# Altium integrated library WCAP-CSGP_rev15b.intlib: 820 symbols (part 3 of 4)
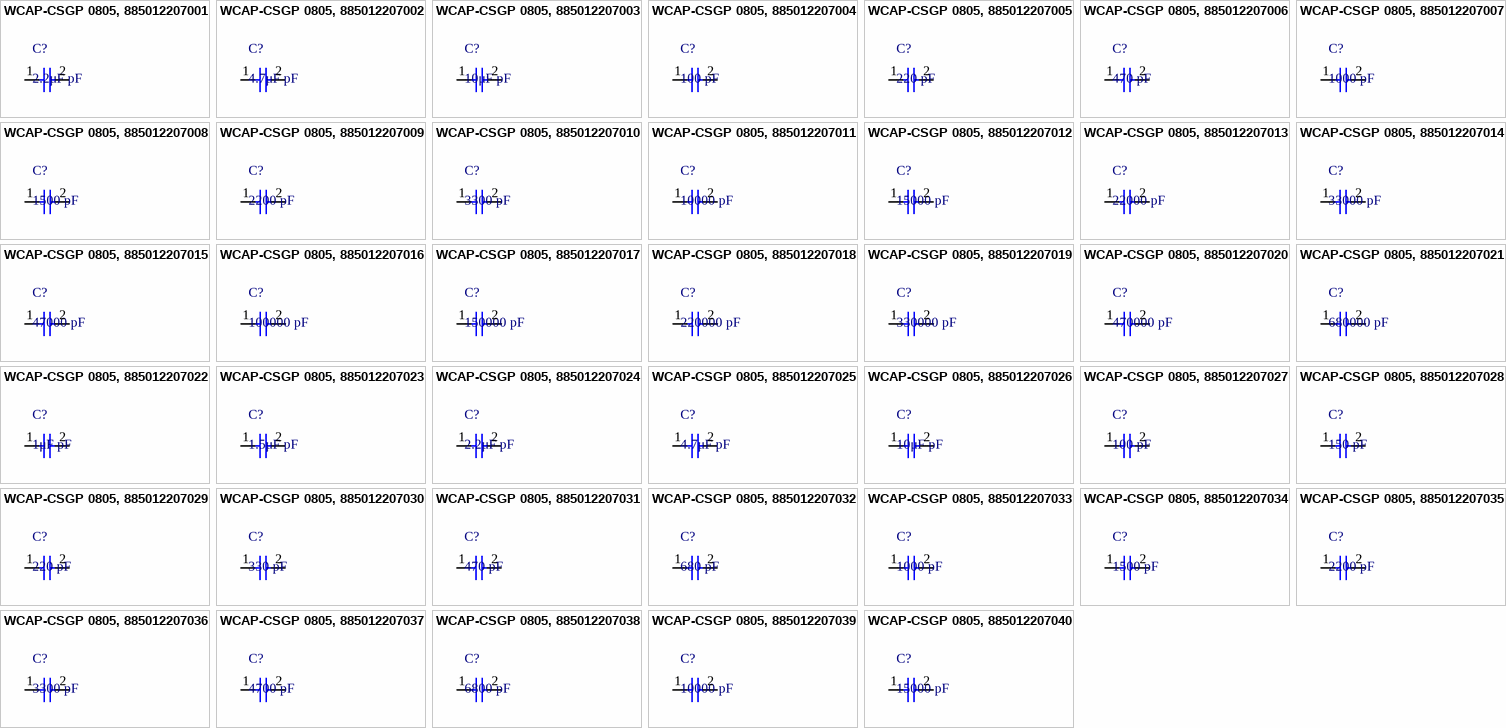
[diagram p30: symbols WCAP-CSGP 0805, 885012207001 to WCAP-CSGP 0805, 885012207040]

## WCAP-CSGP 0805, 885012207004
designator C?, comment 100 pF
WCAP-CSGP MLCC, X7R, 0805, 100 pF,10Vdc; Manufacturer: Wurth Elektronik; partNo: 885012207004; E-mail: libraries@we-online.com
footprint WCAP-CSGP 0805, H=0.8mm
pins: 1, 2

## WCAP-CSGP 0805, 885012207005
designator C?, comment 220 pF
WCAP-CSGP MLCC, X7R, 0805, 220 pF,10Vdc; Manufacturer: Wurth Elektronik; partNo: 885012207005; E-mail: libraries@we-online.com
footprint WCAP-CSGP 0805, H=0.8mm
pins: 1, 2

## WCAP-CSGP 0805, 885012207006
designator C?, comment 470 pF
WCAP-CSGP MLCC, X7R, 0805, 470 pF,10Vdc; Manufacturer: Wurth Elektronik; partNo: 885012207006; E-mail: libraries@we-online.com
footprint WCAP-CSGP 0805, H=0.8mm
pins: 1, 2

## WCAP-CSGP 0805, 885012207007
designator C?, comment 1000 pF
WCAP-CSGP MLCC, X7R, 0805, 1000 pF,10Vdc; Manufacturer: Wurth Elektronik; partNo: 885012207007; E-mail: libraries@we-online.com
footprint WCAP-CSGP 0805, H=0.8mm
pins: 1, 2

## WCAP-CSGP 0805, 885012207008
designator C?, comment 1500 pF
WCAP-CSGP MLCC, X7R, 0805, 1500 pF,10Vdc; Manufacturer: Wurth Elektronik; partNo: 885012207008; E-mail: libraries@we-online.com
footprint WCAP-CSGP 0805, H=0.8mm
pins: 1, 2

## WCAP-CSGP 0805, 885012207009
designator C?, comment 2200 pF
WCAP-CSGP MLCC, X7R, 0805, 2200 pF,10Vdc; Manufacturer: Wurth Elektronik; partNo: 885012207009; E-mail: libraries@we-online.com
footprint WCAP-CSGP 0805, H=0.8mm
pins: 1, 2

## WCAP-CSGP 0805, 885012207010
designator C?, comment 3300 pF
WCAP-CSGP MLCC, X7R, 0805, 3300 pF,10Vdc; Manufacturer: Wurth Elektronik; partNo: 885012207010; E-mail: libraries@we-online.com
footprint WCAP-CSGP 0805, H=0.8mm
pins: 1, 2

## WCAP-CSGP 0805, 885012207011
designator C?, comment 10000 pF
WCAP-CSGP MLCC, X7R, 0805, 10000 pF,10Vdc; Manufacturer: Wurth Elektronik; partNo: 885012207011; E-mail: libraries@we-online.com
footprint WCAP-CSGP 0805, H=0.8mm
pins: 1, 2

## WCAP-CSGP 0805, 885012207012
designator C?, comment 15000 pF
WCAP-CSGP MLCC, X7R, 0805, 15000 pF,10Vdc; Manufacturer: Wurth Elektronik; partNo: 885012207012; E-mail: libraries@we-online.com
footprint WCAP-CSGP 0805, H=0.8mm
pins: 1, 2

## WCAP-CSGP 0805, 885012207013
designator C?, comment 22000 pF
WCAP-CSGP MLCC, X7R, 0805, 22000 pF,10Vdc; Manufacturer: Wurth Elektronik; partNo: 885012207013; E-mail: libraries@we-online.com
footprint WCAP-CSGP 0805, H=0.8mm
pins: 1, 2

## WCAP-CSGP 0805, 885012207014
designator C?, comment 33000 pF
WCAP-CSGP MLCC, X7R, 0805, 33000 pF,10Vdc; Manufacturer: Wurth Elektronik; partNo: 885012207014; E-mail: libraries@we-online.com
footprint WCAP-CSGP 0805, H=0.8mm
pins: 1, 2

## WCAP-CSGP 0805, 885012207015
designator C?, comment 47000 pF
WCAP-CSGP MLCC, X7R, 0805, 47000 pF,10Vdc; Manufacturer: Wurth Elektronik; partNo: 885012207015; E-mail: libraries@we-online.com
footprint WCAP-CSGP 0805, H=0.8mm
pins: 1, 2

## WCAP-CSGP 0805, 885012207016
designator C?, comment 100000 pF
WCAP-CSGP MLCC, X7R, 0805, 100000 pF,10Vdc; Manufacturer: Wurth Elektronik; partNo: 885012207016; E-mail: libraries@we-online.com
footprint WCAP-CSGP 0805, H=0.8mm
pins: 1, 2

## WCAP-CSGP 0805, 885012207017
designator C?, comment 150000 pF
WCAP-CSGP MLCC, X7R, 0805, 150000 pF,10Vdc; Manufacturer: Wurth Elektronik; partNo: 885012207017; E-mail: libraries@we-online.com
footprint WCAP-CSGP 0805, H=1.25mm
pins: 1, 2

## WCAP-CSGP 0805, 885012207018
designator C?, comment 220000 pF
WCAP-CSGP MLCC, X7R, 0805, 220000 pF,10Vdc; Manufacturer: Wurth Elektronik; partNo: 885012207018; E-mail: libraries@we-online.com
footprint WCAP-CSGP 0805, H=1.25mm
pins: 1, 2

## WCAP-CSGP 0805, 885012207019
designator C?, comment 330000 pF
WCAP-CSGP MLCC, X7R, 0805, 330000 pF,10Vdc; Manufacturer: Wurth Elektronik; partNo: 885012207019; E-mail: libraries@we-online.com
footprint WCAP-CSGP 0805, H=1.25mm
pins: 1, 2

## WCAP-CSGP 0805, 885012207020
designator C?, comment 470000 pF
WCAP-CSGP MLCC, X7R, 0805, 470000 pF,10Vdc; Manufacturer: Wurth Elektronik; partNo: 885012207020; E-mail: libraries@we-online.com
footprint WCAP-CSGP 0805, H=1.25mm
pins: 1, 2

## WCAP-CSGP 0805, 885012207021
designator C?, comment 680000 pF
WCAP-CSGP MLCC, X7R, 0805, 680000 pF,10Vdc; Manufacturer: Wurth Elektronik; partNo: 885012207021; E-mail: libraries@we-online.com
footprint WCAP-CSGP 0805, H=1.25mm
pins: 1, 2

## WCAP-CSGP 0805, 885012207022
designator C?, comment 1μF pF
WCAP-CSGP MLCC, X7R, 0805, 1μF pF,10Vdc; Manufacturer: Wurth Elektronik; partNo: 885012207022; E-mail: libraries@we-online.com
footprint WCAP-CSGP 0805, H=1.25mm
pins: 1, 2

## WCAP-CSGP 0805, 885012207023
designator C?, comment 1.5μF pF
WCAP-CSGP MLCC, X7R, 0805, 1.5μF pF,10Vdc; Manufacturer: Wurth Elektronik; partNo: 885012207023; E-mail: libraries@we-online.com
footprint WCAP-CSGP 0805, H=1.25mm
pins: 1, 2

## WCAP-CSGP 0805, 885012207024
designator C?, comment 2.2μF pF
WCAP-CSGP MLCC, X7R, 0805, 2.2μF pF,10Vdc; Manufacturer: Wurth Elektronik; partNo: 885012207024; E-mail: libraries@we-online.com
footprint WCAP-CSGP 0805, H=1.25mm
pins: 1, 2

## WCAP-CSGP 0805, 885012207025
designator C?, comment 4.7μF pF
WCAP-CSGP MLCC, X7R, 0805, 4.7μF pF,10Vdc; Manufacturer: Wurth Elektronik; partNo: 885012207025; E-mail: libraries@we-online.com
footprint WCAP-CSGP 0805, H=1.25mm
pins: 1, 2

## WCAP-CSGP 0805, 885012207026
designator C?, comment 10μF pF
WCAP-CSGP MLCC, X7R, 0805, 10μF pF,10Vdc; Manufacturer: Wurth Elektronik; partNo: 885012207026; E-mail: libraries@we-online.com
footprint WCAP-CSGP 0805, H=1.25mm
pins: 1, 2

## WCAP-CSGP 0805, 885012207027
designator C?, comment 100 pF
WCAP-CSGP MLCC, X7R, 0805, 100 pF,16Vdc; Manufacturer: Wurth Elektronik; partNo: 885012207027; E-mail: libraries@we-online.com
footprint WCAP-CSGP 0805, H=0.8mm
pins: 1, 2

## WCAP-CSGP 0805, 885012207028
designator C?, comment 150 pF
WCAP-CSGP MLCC, X7R, 0805, 150 pF,16Vdc; Manufacturer: Wurth Elektronik; partNo: 885012207028; E-mail: libraries@we-online.com
footprint WCAP-CSGP 0805, H=0.8mm
pins: 1, 2

## WCAP-CSGP 0805, 885012207029
designator C?, comment 220 pF
WCAP-CSGP MLCC, X7R, 0805, 220 pF,16Vdc; Manufacturer: Wurth Elektronik; partNo: 885012207029; E-mail: libraries@we-online.com
footprint WCAP-CSGP 0805, H=0.8mm
pins: 1, 2

## WCAP-CSGP 0805, 885012207030
designator C?, comment 330 pF
WCAP-CSGP MLCC, X7R, 0805, 330 pF,16Vdc; Manufacturer: Wurth Elektronik; partNo: 885012207030; E-mail: libraries@we-online.com
footprint WCAP-CSGP 0805, H=0.8mm
pins: 1, 2

## WCAP-CSGP 0805, 885012207031
designator C?, comment 470 pF
WCAP-CSGP MLCC, X7R, 0805, 470 pF,16Vdc; Manufacturer: Wurth Elektronik; partNo: 885012207031; E-mail: libraries@we-online.com
footprint WCAP-CSGP 0805, H=0.8mm
pins: 1, 2

## WCAP-CSGP 0805, 885012207032
designator C?, comment 680 pF
WCAP-CSGP MLCC, X7R, 0805, 680 pF,16Vdc; Manufacturer: Wurth Elektronik; partNo: 885012207032; E-mail: libraries@we-online.com
footprint WCAP-CSGP 0805, H=0.8mm
pins: 1, 2

## WCAP-CSGP 0805, 885012207033
designator C?, comment 1000 pF
WCAP-CSGP MLCC, X7R, 0805, 1000 pF,16Vdc; Manufacturer: Wurth Elektronik; partNo: 885012207033; E-mail: libraries@we-online.com
footprint WCAP-CSGP 0805, H=0.8mm
pins: 1, 2

## WCAP-CSGP 0805, 885012207034
designator C?, comment 1500 pF
WCAP-CSGP MLCC, X7R, 0805, 1500 pF,16Vdc; Manufacturer: Wurth Elektronik; partNo: 885012207034; E-mail: libraries@we-online.com
footprint WCAP-CSGP 0805, H=0.8mm
pins: 1, 2

## WCAP-CSGP 0805, 885012207035
designator C?, comment 2200 pF
WCAP-CSGP MLCC, X7R, 0805, 2200 pF,16Vdc; Manufacturer: Wurth Elektronik; partNo: 885012207035; E-mail: libraries@we-online.com
footprint WCAP-CSGP 0805, H=0.8mm
pins: 1, 2

## WCAP-CSGP 0805, 885012207036
designator C?, comment 3300 pF
WCAP-CSGP MLCC, X7R, 0805, 3300 pF,16Vdc; Manufacturer: Wurth Elektronik; partNo: 885012207036; E-mail: libraries@we-online.com
footprint WCAP-CSGP 0805, H=0.8mm
pins: 1, 2

## WCAP-CSGP 0805, 885012207037
designator C?, comment 4700 pF
WCAP-CSGP MLCC, X7R, 0805, 4700 pF,16Vdc; Manufacturer: Wurth Elektronik; partNo: 885012207037; E-mail: libraries@we-online.com
footprint WCAP-CSGP 0805, H=0.8mm
pins: 1, 2

## WCAP-CSGP 0805, 885012207038
designator C?, comment 6800 pF
WCAP-CSGP MLCC, X7R, 0805, 6800 pF,16Vdc; Manufacturer: Wurth Elektronik; partNo: 885012207038; E-mail: libraries@we-online.com
footprint WCAP-CSGP 0805, H=0.8mm
pins: 1, 2

## WCAP-CSGP 0805, 885012207039
designator C?, comment 10000 pF
WCAP-CSGP MLCC, X7R, 0805, 10000 pF,16Vdc; Manufacturer: Wurth Elektronik; partNo: 885012207039; E-mail: libraries@we-online.com
footprint WCAP-CSGP 0805, H=0.8mm
pins: 1, 2

## WCAP-CSGP 0805, 885012207040
designator C?, comment 15000 pF
WCAP-CSGP MLCC, X7R, 0805, 15000 pF,16Vdc; Manufacturer: Wurth Elektronik; partNo: 885012207040; E-mail: libraries@we-online.com
footprint WCAP-CSGP 0805, H=0.8mm
pins: 1, 2

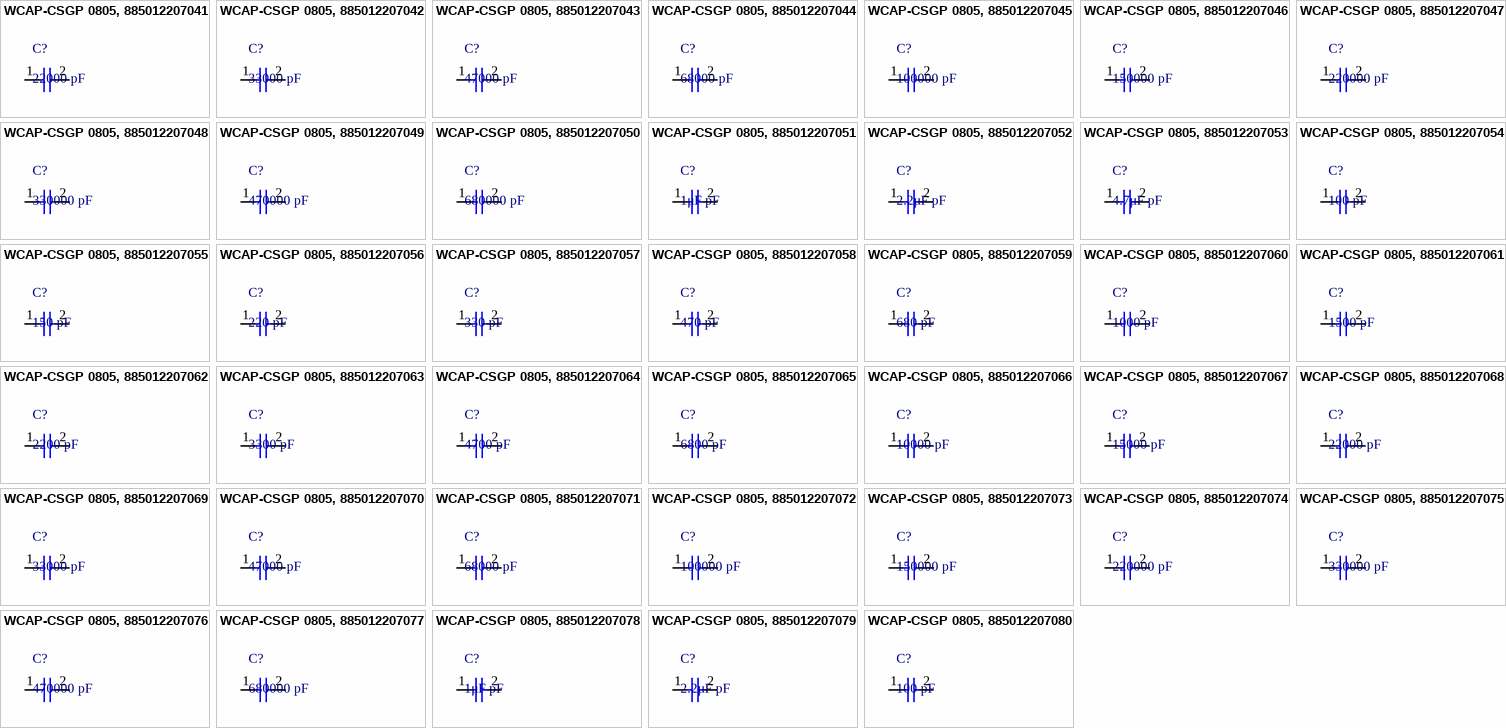
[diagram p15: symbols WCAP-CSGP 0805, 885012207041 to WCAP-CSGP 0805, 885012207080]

## WCAP-CSGP 0805, 885012207041
designator C?, comment 22000 pF
WCAP-CSGP MLCC, X7R, 0805, 22000 pF,16Vdc; Manufacturer: Wurth Elektronik; partNo: 885012207041; E-mail: libraries@we-online.com
footprint WCAP-CSGP 0805, H=0.8mm
pins: 1, 2

## WCAP-CSGP 0805, 885012207042
designator C?, comment 33000 pF
WCAP-CSGP MLCC, X7R, 0805, 33000 pF,16Vdc; Manufacturer: Wurth Elektronik; partNo: 885012207042; E-mail: libraries@we-online.com
footprint WCAP-CSGP 0805, H=0.8mm
pins: 1, 2

## WCAP-CSGP 0805, 885012207043
designator C?, comment 47000 pF
WCAP-CSGP MLCC, X7R, 0805, 47000 pF,16Vdc; Manufacturer: Wurth Elektronik; partNo: 885012207043; E-mail: libraries@we-online.com
footprint WCAP-CSGP 0805, H=0.8mm
pins: 1, 2

## WCAP-CSGP 0805, 885012207044
designator C?, comment 68000 pF
WCAP-CSGP MLCC, X7R, 0805, 68000 pF,16Vdc; Manufacturer: Wurth Elektronik; partNo: 885012207044; E-mail: libraries@we-online.com
footprint WCAP-CSGP 0805, H=0.8mm
pins: 1, 2

## WCAP-CSGP 0805, 885012207045
designator C?, comment 100000 pF
WCAP-CSGP MLCC, X7R, 0805, 100000 pF,16Vdc; Manufacturer: Wurth Elektronik; partNo: 885012207045; E-mail: libraries@we-online.com
footprint WCAP-CSGP 0805, H=0.8mm
pins: 1, 2

## WCAP-CSGP 0805, 885012207046
designator C?, comment 150000 pF
WCAP-CSGP MLCC, X7R, 0805, 150000 pF,16Vdc; Manufacturer: Wurth Elektronik; partNo: 885012207046; E-mail: libraries@we-online.com
footprint WCAP-CSGP 0805, H=1.25mm
pins: 1, 2

## WCAP-CSGP 0805, 885012207047
designator C?, comment 220000 pF
WCAP-CSGP MLCC, X7R, 0805, 220000 pF,16Vdc; Manufacturer: Wurth Elektronik; partNo: 885012207047; E-mail: libraries@we-online.com
footprint WCAP-CSGP 0805, H=1.25mm
pins: 1, 2

## WCAP-CSGP 0805, 885012207048
designator C?, comment 330000 pF
WCAP-CSGP MLCC, X7R, 0805, 330000 pF,16Vdc; Manufacturer: Wurth Elektronik; partNo: 885012207048; E-mail: libraries@we-online.com
footprint WCAP-CSGP 0805, H=1.25mm
pins: 1, 2

## WCAP-CSGP 0805, 885012207049
designator C?, comment 470000 pF
WCAP-CSGP MLCC, X7R, 0805, 470000 pF,16Vdc; Manufacturer: Wurth Elektronik; partNo: 885012207049; E-mail: libraries@we-online.com
footprint WCAP-CSGP 0805, H=1.25mm
pins: 1, 2

## WCAP-CSGP 0805, 885012207050
designator C?, comment 680000 pF
WCAP-CSGP MLCC, X7R, 0805, 680000 pF,16Vdc; Manufacturer: Wurth Elektronik; partNo: 885012207050; E-mail: libraries@we-online.com
footprint WCAP-CSGP 0805, H=1.25mm
pins: 1, 2

## WCAP-CSGP 0805, 885012207051
designator C?, comment 1μF pF
WCAP-CSGP MLCC, X7R, 0805, 1μF pF,16Vdc; Manufacturer: Wurth Elektronik; partNo: 885012207051; E-mail: libraries@we-online.com
footprint WCAP-CSGP 0805, H=1.25mm
pins: 1, 2

## WCAP-CSGP 0805, 885012207052
designator C?, comment 2.2μF pF
WCAP-CSGP MLCC, X7R, 0805, 2.2μF pF,16Vdc; Manufacturer: Wurth Elektronik; partNo: 885012207052; E-mail: libraries@we-online.com
footprint WCAP-CSGP 0805, H=1.25mm
pins: 1, 2

## WCAP-CSGP 0805, 885012207053
designator C?, comment 4.7μF pF
WCAP-CSGP MLCC, X7R, 0805, 4.7μF pF,16Vdc; Manufacturer: Wurth Elektronik; partNo: 885012207053; E-mail: libraries@we-online.com
footprint WCAP-CSGP 0805, H=1.25mm
pins: 1, 2

## WCAP-CSGP 0805, 885012207054
designator C?, comment 100 pF
WCAP-CSGP MLCC, X7R, 0805, 100 pF,25Vdc; Manufacturer: Wurth Elektronik; partNo: 885012207054; E-mail: libraries@we-online.com
footprint WCAP-CSGP 0805, H=0.8mm
pins: 1, 2

## WCAP-CSGP 0805, 885012207055
designator C?, comment 150 pF
WCAP-CSGP MLCC, X7R, 0805, 150 pF,25Vdc; Manufacturer: Wurth Elektronik; partNo: 885012207055; E-mail: libraries@we-online.com
footprint WCAP-CSGP 0805, H=0.8mm
pins: 1, 2

## WCAP-CSGP 0805, 885012207056
designator C?, comment 220 pF
WCAP-CSGP MLCC, X7R, 0805, 220 pF,25Vdc; Manufacturer: Wurth Elektronik; partNo: 885012207056; E-mail: libraries@we-online.com
footprint WCAP-CSGP 0805, H=0.8mm
pins: 1, 2

## WCAP-CSGP 0805, 885012207057
designator C?, comment 330 pF
WCAP-CSGP MLCC, X7R, 0805, 330 pF,25Vdc; Manufacturer: Wurth Elektronik; partNo: 885012207057; E-mail: libraries@we-online.com
footprint WCAP-CSGP 0805, H=0.8mm
pins: 1, 2

## WCAP-CSGP 0805, 885012207058
designator C?, comment 470 pF
WCAP-CSGP MLCC, X7R, 0805, 470 pF,25Vdc; Manufacturer: Wurth Elektronik; partNo: 885012207058; E-mail: libraries@we-online.com
footprint WCAP-CSGP 0805, H=0.8mm
pins: 1, 2

## WCAP-CSGP 0805, 885012207059
designator C?, comment 680 pF
WCAP-CSGP MLCC, X7R, 0805, 680 pF,25Vdc; Manufacturer: Wurth Elektronik; partNo: 885012207059; E-mail: libraries@we-online.com
footprint WCAP-CSGP 0805, H=0.8mm
pins: 1, 2

## WCAP-CSGP 0805, 885012207060
designator C?, comment 1000 pF
WCAP-CSGP MLCC, X7R, 0805, 1000 pF,25Vdc; Manufacturer: Wurth Elektronik; partNo: 885012207060; E-mail: libraries@we-online.com
footprint WCAP-CSGP 0805, H=0.8mm
pins: 1, 2

## WCAP-CSGP 0805, 885012207061
designator C?, comment 1500 pF
WCAP-CSGP MLCC, X7R, 0805, 1500 pF,25Vdc; Manufacturer: Wurth Elektronik; partNo: 885012207061; E-mail: libraries@we-online.com
footprint WCAP-CSGP 0805, H=0.8mm
pins: 1, 2

## WCAP-CSGP 0805, 885012207062
designator C?, comment 2200 pF
WCAP-CSGP MLCC, X7R, 0805, 2200 pF,25Vdc; Manufacturer: Wurth Elektronik; partNo: 885012207062; E-mail: libraries@we-online.com
footprint WCAP-CSGP 0805, H=0.8mm
pins: 1, 2

## WCAP-CSGP 0805, 885012207063
designator C?, comment 3300 pF
WCAP-CSGP MLCC, X7R, 0805, 3300 pF,25Vdc; Manufacturer: Wurth Elektronik; partNo: 885012207063; E-mail: libraries@we-online.com
footprint WCAP-CSGP 0805, H=0.8mm
pins: 1, 2

## WCAP-CSGP 0805, 885012207064
designator C?, comment 4700 pF
WCAP-CSGP MLCC, X7R, 0805, 4700 pF,25Vdc; Manufacturer: Wurth Elektronik; partNo: 885012207064; E-mail: libraries@we-online.com
footprint WCAP-CSGP 0805, H=0.8mm
pins: 1, 2

## WCAP-CSGP 0805, 885012207065
designator C?, comment 6800 pF
WCAP-CSGP MLCC, X7R, 0805, 6800 pF,25Vdc; Manufacturer: Wurth Elektronik; partNo: 885012207065; E-mail: libraries@we-online.com
footprint WCAP-CSGP 0805, H=0.8mm
pins: 1, 2

## WCAP-CSGP 0805, 885012207066
designator C?, comment 10000 pF
WCAP-CSGP MLCC, X7R, 0805, 10000 pF,25Vdc; Manufacturer: Wurth Elektronik; partNo: 885012207066; E-mail: libraries@we-online.com
footprint WCAP-CSGP 0805, H=0.8mm
pins: 1, 2

## WCAP-CSGP 0805, 885012207067
designator C?, comment 15000 pF
WCAP-CSGP MLCC, X7R, 0805, 15000 pF,25Vdc; Manufacturer: Wurth Elektronik; partNo: 885012207067; E-mail: libraries@we-online.com
footprint WCAP-CSGP 0805, H=0.8mm
pins: 1, 2

## WCAP-CSGP 0805, 885012207068
designator C?, comment 22000 pF
WCAP-CSGP MLCC, X7R, 0805, 22000 pF,25Vdc; Manufacturer: Wurth Elektronik; partNo: 885012207068; E-mail: libraries@we-online.com
footprint WCAP-CSGP 0805, H=0.8mm
pins: 1, 2

## WCAP-CSGP 0805, 885012207069
designator C?, comment 33000 pF
WCAP-CSGP MLCC, X7R, 0805, 33000 pF,25Vdc; Manufacturer: Wurth Elektronik; partNo: 885012207069; E-mail: libraries@we-online.com
footprint WCAP-CSGP 0805, H=0.8mm
pins: 1, 2

## WCAP-CSGP 0805, 885012207070
designator C?, comment 47000 pF
WCAP-CSGP MLCC, X7R, 0805, 47000 pF,25Vdc; Manufacturer: Wurth Elektronik; partNo: 885012207070; E-mail: libraries@we-online.com
footprint WCAP-CSGP 0805, H=0.8mm
pins: 1, 2

## WCAP-CSGP 0805, 885012207071
designator C?, comment 68000 pF
WCAP-CSGP MLCC, X7R, 0805, 68000 pF,25Vdc; Manufacturer: Wurth Elektronik; partNo: 885012207071; E-mail: libraries@we-online.com
footprint WCAP-CSGP 0805, H=0.8mm
pins: 1, 2

## WCAP-CSGP 0805, 885012207072
designator C?, comment 100000 pF
WCAP-CSGP MLCC, X7R, 0805, 100000 pF,25Vdc; Manufacturer: Wurth Elektronik; partNo: 885012207072; E-mail: libraries@we-online.com
footprint WCAP-CSGP 0805, H=0.8mm
pins: 1, 2

## WCAP-CSGP 0805, 885012207073
designator C?, comment 150000 pF
WCAP-CSGP MLCC, X7R, 0805, 150000 pF,25Vdc; Manufacturer: Wurth Elektronik; partNo: 885012207073; E-mail: libraries@we-online.com
footprint WCAP-CSGP 0805, H=1.25mm
pins: 1, 2

## WCAP-CSGP 0805, 885012207074
designator C?, comment 220000 pF
WCAP-CSGP MLCC, X7R, 0805, 220000 pF,25Vdc; Manufacturer: Wurth Elektronik; partNo: 885012207074; E-mail: libraries@we-online.com
footprint WCAP-CSGP 0805, H=1.25mm
pins: 1, 2

## WCAP-CSGP 0805, 885012207075
designator C?, comment 330000 pF
WCAP-CSGP MLCC, X7R, 0805, 330000 pF,25Vdc; Manufacturer: Wurth Elektronik; partNo: 885012207075; E-mail: libraries@we-online.com
footprint WCAP-CSGP 0805, H=1.25mm
pins: 1, 2

## WCAP-CSGP 0805, 885012207076
designator C?, comment 470000 pF
WCAP-CSGP MLCC, X7R, 0805, 470000 pF,25Vdc; Manufacturer: Wurth Elektronik; partNo: 885012207076; E-mail: libraries@we-online.com
footprint WCAP-CSGP 0805, H=1.25mm
pins: 1, 2

## WCAP-CSGP 0805, 885012207077
designator C?, comment 680000 pF
WCAP-CSGP MLCC, X7R, 0805, 680000 pF,25Vdc; Manufacturer: Wurth Elektronik; partNo: 885012207077; E-mail: libraries@we-online.com
footprint WCAP-CSGP 0805, H=1.25mm
pins: 1, 2

## WCAP-CSGP 0805, 885012207078
designator C?, comment 1μF pF
WCAP-CSGP MLCC, X7R, 0805, 1μF pF,25Vdc; Manufacturer: Wurth Elektronik; partNo: 885012207078; E-mail: libraries@we-online.com
footprint WCAP-CSGP 0805, H=1.25mm
pins: 1, 2

## WCAP-CSGP 0805, 885012207079
designator C?, comment 2.2μF pF
WCAP-CSGP MLCC, X7R, 0805, 2.2μF pF,25Vdc; Manufacturer: Wurth Elektronik; partNo: 885012207079; E-mail: libraries@we-online.com
footprint WCAP-CSGP 0805, H=1.25mm
pins: 1, 2

## WCAP-CSGP 0805, 885012207080
designator C?, comment 100 pF
WCAP-CSGP MLCC, X7R, 0805, 100 pF,50Vdc; Manufacturer: Wurth Elektronik; partNo: 885012207080; E-mail: libraries@we-online.com
footprint WCAP-CSGP 0805, H=0.8mm
pins: 1, 2

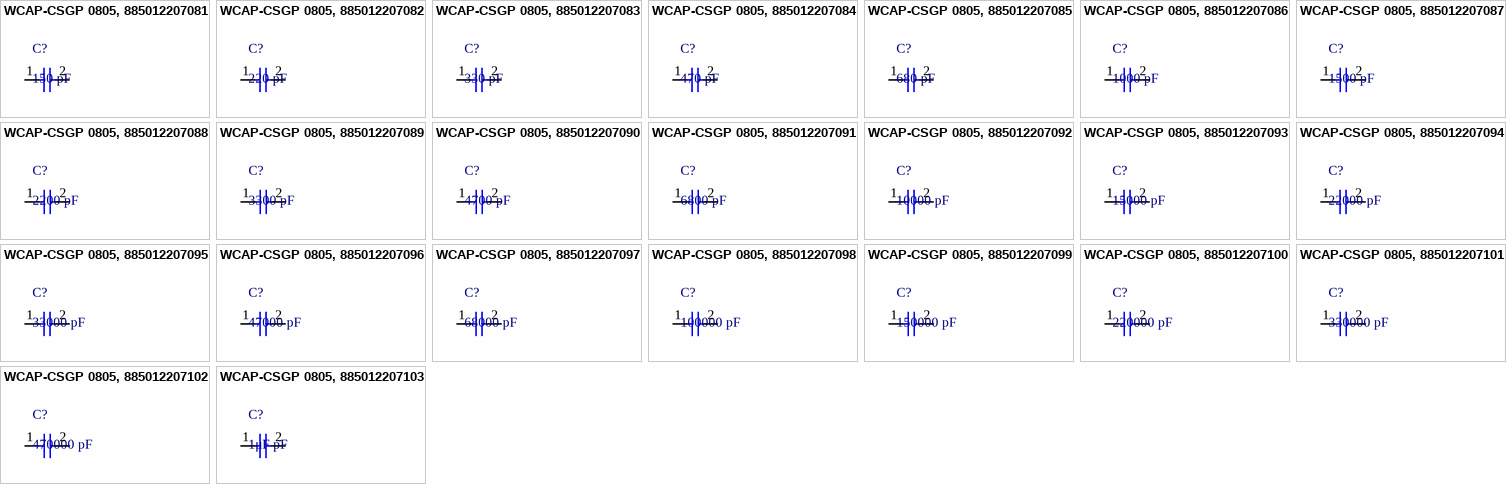
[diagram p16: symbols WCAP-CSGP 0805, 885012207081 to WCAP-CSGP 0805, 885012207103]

## WCAP-CSGP 0805, 885012207081
designator C?, comment 150 pF
WCAP-CSGP MLCC, X7R, 0805, 150 pF,50Vdc; Manufacturer: Wurth Elektronik; partNo: 885012207081; E-mail: libraries@we-online.com
footprint WCAP-CSGP 0805, H=0.8mm
pins: 1, 2

## WCAP-CSGP 0805, 885012207082
designator C?, comment 220 pF
WCAP-CSGP MLCC, X7R, 0805, 220 pF,50Vdc; Manufacturer: Wurth Elektronik; partNo: 885012207082; E-mail: libraries@we-online.com
footprint WCAP-CSGP 0805, H=0.8mm
pins: 1, 2

## WCAP-CSGP 0805, 885012207083
designator C?, comment 330 pF
WCAP-CSGP MLCC, X7R, 0805, 330 pF,50Vdc; Manufacturer: Wurth Elektronik; partNo: 885012207083; E-mail: libraries@we-online.com
footprint WCAP-CSGP 0805, H=0.8mm
pins: 1, 2

## WCAP-CSGP 0805, 885012207084
designator C?, comment 470 pF
WCAP-CSGP MLCC, X7R, 0805, 470 pF,50Vdc; Manufacturer: Wurth Elektronik; partNo: 885012207084; E-mail: libraries@we-online.com
footprint WCAP-CSGP 0805, H=0.8mm
pins: 1, 2

## WCAP-CSGP 0805, 885012207085
designator C?, comment 680 pF
WCAP-CSGP MLCC, X7R, 0805, 680 pF,50Vdc; Manufacturer: Wurth Elektronik; partNo: 885012207085; E-mail: libraries@we-online.com
footprint WCAP-CSGP 0805, H=0.8mm
pins: 1, 2

## WCAP-CSGP 0805, 885012207086
designator C?, comment 1000 pF
WCAP-CSGP MLCC, X7R, 0805, 1000 pF,50Vdc; Manufacturer: Wurth Elektronik; partNo: 885012207086; E-mail: libraries@we-online.com
footprint WCAP-CSGP 0805, H=0.8mm
pins: 1, 2

## WCAP-CSGP 0805, 885012207087
designator C?, comment 1500 pF
WCAP-CSGP MLCC, X7R, 0805, 1500 pF,50Vdc; Manufacturer: Wurth Elektronik; partNo: 885012207087; E-mail: libraries@we-online.com
footprint WCAP-CSGP 0805, H=0.8mm
pins: 1, 2

## WCAP-CSGP 0805, 885012207088
designator C?, comment 2200 pF
WCAP-CSGP MLCC, X7R, 0805, 2200 pF,50Vdc; Manufacturer: Wurth Elektronik; partNo: 885012207088; E-mail: libraries@we-online.com
footprint WCAP-CSGP 0805, H=0.8mm
pins: 1, 2

## WCAP-CSGP 0805, 885012207089
designator C?, comment 3300 pF
WCAP-CSGP MLCC, X7R, 0805, 3300 pF,50Vdc; Manufacturer: Wurth Elektronik; partNo: 885012207089; E-mail: libraries@we-online.com
footprint WCAP-CSGP 0805, H=0.8mm
pins: 1, 2

## WCAP-CSGP 0805, 885012207090
designator C?, comment 4700 pF
WCAP-CSGP MLCC, X7R, 0805, 4700 pF,50Vdc; Manufacturer: Wurth Elektronik; partNo: 885012207090; E-mail: libraries@we-online.com
footprint WCAP-CSGP 0805, H=0.8mm
pins: 1, 2

## WCAP-CSGP 0805, 885012207091
designator C?, comment 6800 pF
WCAP-CSGP MLCC, X7R, 0805, 6800 pF,50Vdc; Manufacturer: Wurth Elektronik; partNo: 885012207091; E-mail: libraries@we-online.com
footprint WCAP-CSGP 0805, H=0.8mm
pins: 1, 2

## WCAP-CSGP 0805, 885012207092
designator C?, comment 10000 pF
WCAP-CSGP MLCC, X7R, 0805, 10000 pF,50Vdc; Manufacturer: Wurth Elektronik; partNo: 885012207092; E-mail: libraries@we-online.com
footprint WCAP-CSGP 0805, H=0.8mm
pins: 1, 2

## WCAP-CSGP 0805, 885012207093
designator C?, comment 15000 pF
WCAP-CSGP MLCC, X7R, 0805, 15000 pF,50Vdc; Manufacturer: Wurth Elektronik; partNo: 885012207093; E-mail: libraries@we-online.com
footprint WCAP-CSGP 0805, H=0.8mm
pins: 1, 2

## WCAP-CSGP 0805, 885012207094
designator C?, comment 22000 pF
WCAP-CSGP MLCC, X7R, 0805, 22000 pF,50Vdc; Manufacturer: Wurth Elektronik; partNo: 885012207094; E-mail: libraries@we-online.com
footprint WCAP-CSGP 0805, H=0.8mm
pins: 1, 2

## WCAP-CSGP 0805, 885012207095
designator C?, comment 33000 pF
WCAP-CSGP MLCC, X7R, 0805, 33000 pF,50Vdc; Manufacturer: Wurth Elektronik; partNo: 885012207095; E-mail: libraries@we-online.com
footprint WCAP-CSGP 0805, H=0.8mm
pins: 1, 2

## WCAP-CSGP 0805, 885012207096
designator C?, comment 47000 pF
WCAP-CSGP MLCC, X7R, 0805, 47000 pF,50Vdc; Manufacturer: Wurth Elektronik; partNo: 885012207096; E-mail: libraries@we-online.com
footprint WCAP-CSGP 0805, H=0.8mm
pins: 1, 2

## WCAP-CSGP 0805, 885012207097
designator C?, comment 68000 pF
WCAP-CSGP MLCC, X7R, 0805, 68000 pF,50Vdc; Manufacturer: Wurth Elektronik; partNo: 885012207097; E-mail: libraries@we-online.com
footprint WCAP-CSGP 0805, H=0.8mm
pins: 1, 2

## WCAP-CSGP 0805, 885012207098
designator C?, comment 100000 pF
WCAP-CSGP MLCC, X7R, 0805, 100000 pF,50Vdc; Manufacturer: Wurth Elektronik; partNo: 885012207098; E-mail: libraries@we-online.com
footprint WCAP-CSGP 0805, H=0.8mm
pins: 1, 2

## WCAP-CSGP 0805, 885012207099
designator C?, comment 150000 pF
WCAP-CSGP MLCC, X7R, 0805, 150000 pF,50Vdc; Manufacturer: Wurth Elektronik; partNo: 885012207099; E-mail: libraries@we-online.com
footprint WCAP-CSGP 0805, H=1.25mm
pins: 1, 2

## WCAP-CSGP 0805, 885012207100
designator C?, comment 220000 pF
WCAP-CSGP MLCC, X7R, 0805, 220000 pF,50Vdc; Manufacturer: Wurth Elektronik; partNo: 885012207100; E-mail: libraries@we-online.com
footprint WCAP-CSGP 0805, H=1.25mm
pins: 1, 2

## WCAP-CSGP 0805, 885012207101
designator C?, comment 330000 pF
WCAP-CSGP MLCC, X7R, 0805, 330000 pF,50Vdc; Manufacturer: Wurth Elektronik; partNo: 885012207101; E-mail: libraries@we-online.com
footprint WCAP-CSGP 0805, H=1.25mm
pins: 1, 2

## WCAP-CSGP 0805, 885012207102
designator C?, comment 470000 pF
WCAP-CSGP MLCC, X7R, 0805, 470000 pF,50Vdc; Manufacturer: Wurth Elektronik; partNo: 885012207102; E-mail: libraries@we-online.com
footprint WCAP-CSGP 0805, H=1.25mm
pins: 1, 2

## WCAP-CSGP 0805, 885012207103
designator C?, comment 1μF pF
WCAP-CSGP MLCC, X7R, 0805, 1μF pF,50Vdc; Manufacturer: Wurth Elektronik; partNo: 885012207103; E-mail: libraries@we-online.com
footprint WCAP-CSGP 0805, H=1.25mm
pins: 1, 2


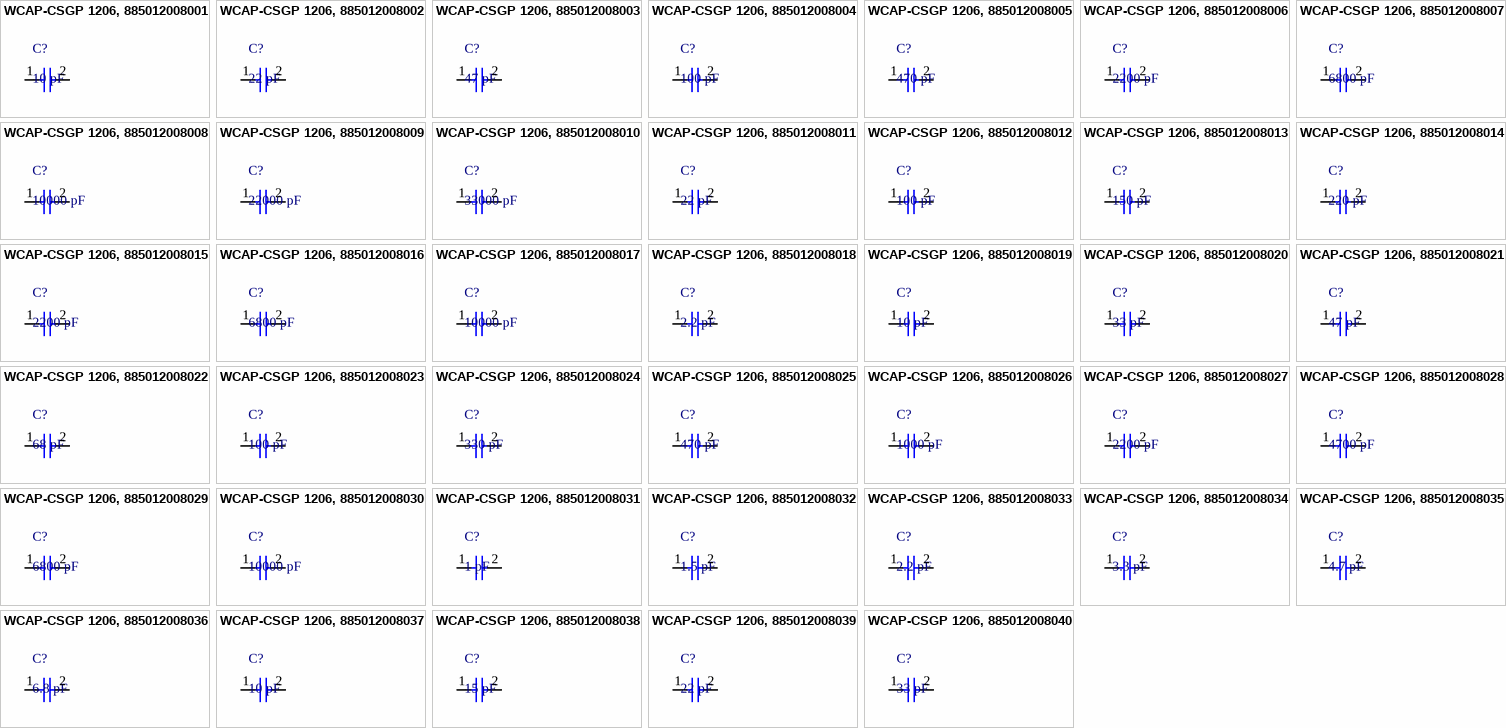
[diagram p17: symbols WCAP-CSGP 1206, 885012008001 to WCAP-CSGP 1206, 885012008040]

## WCAP-CSGP 1206, 885012008001
designator C?, comment 10 pF
WCAP-CSGP MLCC, NP0, 1206, 10 pF,10Vdc; Manufacturer: Wurth Elektronik; partNo: 885012008001; E-mail: libraries@we-online.com
footprint WCAP-CSGP 1206, H=0.8mm
pins: 1, 2

## WCAP-CSGP 1206, 885012008002
designator C?, comment 22 pF
WCAP-CSGP MLCC, NP0, 1206, 22 pF,10Vdc; Manufacturer: Wurth Elektronik; partNo: 885012008002; E-mail: libraries@we-online.com
footprint WCAP-CSGP 1206, H=0.8mm
pins: 1, 2

## WCAP-CSGP 1206, 885012008003
designator C?, comment 47 pF
WCAP-CSGP MLCC, NP0, 1206, 47 pF,10Vdc; Manufacturer: Wurth Elektronik; partNo: 885012008003; E-mail: libraries@we-online.com
footprint WCAP-CSGP 1206, H=0.8mm
pins: 1, 2

## WCAP-CSGP 1206, 885012008004
designator C?, comment 100 pF
WCAP-CSGP MLCC, NP0, 1206, 100 pF,10Vdc; Manufacturer: Wurth Elektronik; partNo: 885012008004; E-mail: libraries@we-online.com
footprint WCAP-CSGP 1206, H=0.8mm
pins: 1, 2

## WCAP-CSGP 1206, 885012008005
designator C?, comment 470 pF
WCAP-CSGP MLCC, NP0, 1206, 470 pF,10Vdc; Manufacturer: Wurth Elektronik; partNo: 885012008005; E-mail: libraries@we-online.com
footprint WCAP-CSGP 1206, H=0.8mm
pins: 1, 2

## WCAP-CSGP 1206, 885012008006
designator C?, comment 2200 pF
WCAP-CSGP MLCC, NP0, 1206, 2200 pF,10Vdc; Manufacturer: Wurth Elektronik; partNo: 885012008006; E-mail: libraries@we-online.com
footprint WCAP-CSGP 1206, H=0.8mm
pins: 1, 2

## WCAP-CSGP 1206, 885012008007
designator C?, comment 6800 pF
WCAP-CSGP MLCC, NP0, 1206, 6800 pF,10Vdc; Manufacturer: Wurth Elektronik; partNo: 885012008007; E-mail: libraries@we-online.com
footprint WCAP-CSGP 1206, H=0.95mm
pins: 1, 2

## WCAP-CSGP 1206, 885012008008
designator C?, comment 10000 pF
WCAP-CSGP MLCC, NP0, 1206, 10000 pF,10Vdc; Manufacturer: Wurth Elektronik; partNo: 885012008008; E-mail: libraries@we-online.com
footprint WCAP-CSGP 1206, H=1.25mm
pins: 1, 2

## WCAP-CSGP 1206, 885012008009
designator C?, comment 22000 pF
WCAP-CSGP MLCC, NP0, 1206, 22000 pF,10Vdc; Manufacturer: Wurth Elektronik; partNo: 885012008009; E-mail: libraries@we-online.com
footprint WCAP-CSGP 1206, H=1.25mm (MLCC 1206, H=1.25mm)
pins: 1, 2

## WCAP-CSGP 1206, 885012008010
designator C?, comment 33000 pF
WCAP-CSGP MLCC, NP0, 1206, 33000 pF,10Vdc; Manufacturer: Wurth Elektronik; partNo: 885012008010; E-mail: libraries@we-online.com
footprint WCAP-CSGP 1206, H=0.85mm
pins: 1, 2

## WCAP-CSGP 1206, 885012008011
designator C?, comment 22 pF
WCAP-CSGP MLCC, NP0, 1206, 22 pF,16Vdc; Manufacturer: Wurth Elektronik; partNo: 885012008011; E-mail: libraries@we-online.com
footprint WCAP-CSGP 1206, H=0.8mm
pins: 1, 2

## WCAP-CSGP 1206, 885012008012
designator C?, comment 100 pF
WCAP-CSGP MLCC, NP0, 1206, 100 pF,16Vdc; Manufacturer: Wurth Elektronik; partNo: 885012008012; E-mail: libraries@we-online.com
footprint WCAP-CSGP 1206, H=0.8mm
pins: 1, 2

## WCAP-CSGP 1206, 885012008013
designator C?, comment 150 pF
WCAP-CSGP MLCC, NP0, 1206, 150 pF,16Vdc; Manufacturer: Wurth Elektronik; partNo: 885012008013; E-mail: libraries@we-online.com
footprint WCAP-CSGP 1206, H=0.8mm
pins: 1, 2

## WCAP-CSGP 1206, 885012008014
designator C?, comment 220 pF
WCAP-CSGP MLCC, NP0, 1206, 220 pF,16Vdc; Manufacturer: Wurth Elektronik; partNo: 885012008014; E-mail: libraries@we-online.com
footprint WCAP-CSGP 1206, H=0.8mm
pins: 1, 2

## WCAP-CSGP 1206, 885012008015
designator C?, comment 2200 pF
WCAP-CSGP MLCC, NP0, 1206, 2200 pF,16Vdc; Manufacturer: Wurth Elektronik; partNo: 885012008015; E-mail: libraries@we-online.com
footprint WCAP-CSGP 1206, H=0.8mm
pins: 1, 2

## WCAP-CSGP 1206, 885012008016
designator C?, comment 6800 pF
WCAP-CSGP MLCC, NP0, 1206, 6800 pF,16Vdc; Manufacturer: Wurth Elektronik; partNo: 885012008016; E-mail: libraries@we-online.com
footprint WCAP-CSGP 1206, H=0.85mm
pins: 1, 2

## WCAP-CSGP 1206, 885012008017
designator C?, comment 10000 pF
WCAP-CSGP MLCC, NP0, 1206, 10000 pF,16Vdc; Manufacturer: Wurth Elektronik; partNo: 885012008017; E-mail: libraries@we-online.com
footprint WCAP-CSGP 1206, H=1.25mm
pins: 1, 2

## WCAP-CSGP 1206, 885012008018
designator C?, comment 2.2 pF
WCAP-CSGP MLCC, NP0, 1206, 2.2 pF,25Vdc; Manufacturer: Wurth Elektronik; partNo: 885012008018; E-mail: libraries@we-online.com
footprint WCAP-CSGP 1206, H=0.8mm
pins: 1, 2

## WCAP-CSGP 1206, 885012008019
designator C?, comment 10 pF
WCAP-CSGP MLCC, NP0, 1206, 10 pF,25Vdc; Manufacturer: Wurth Elektronik; partNo: 885012008019; E-mail: libraries@we-online.com
footprint WCAP-CSGP 1206, H=0.8mm
pins: 1, 2

## WCAP-CSGP 1206, 885012008020
designator C?, comment 33 pF
WCAP-CSGP MLCC, NP0, 1206, 33 pF,25Vdc; Manufacturer: Wurth Elektronik; partNo: 885012008020; E-mail: libraries@we-online.com
footprint WCAP-CSGP 1206, H=0.8mm
pins: 1, 2

## WCAP-CSGP 1206, 885012008021
designator C?, comment 47 pF
WCAP-CSGP MLCC, NP0, 1206, 47 pF,25Vdc; Manufacturer: Wurth Elektronik; partNo: 885012008021; E-mail: libraries@we-online.com
footprint WCAP-CSGP 1206, H=0.8mm
pins: 1, 2

## WCAP-CSGP 1206, 885012008022
designator C?, comment 68 pF
WCAP-CSGP MLCC, NP0, 1206, 68 pF,25Vdc; Manufacturer: Wurth Elektronik; partNo: 885012008022; E-mail: libraries@we-online.com
footprint WCAP-CSGP 1206, H=0.8mm
pins: 1, 2

## WCAP-CSGP 1206, 885012008023
designator C?, comment 100 pF
WCAP-CSGP MLCC, NP0, 1206, 100 pF,25Vdc; Manufacturer: Wurth Elektronik; partNo: 885012008023; E-mail: libraries@we-online.com
footprint WCAP-CSGP 1206, H=0.8mm
pins: 1, 2

## WCAP-CSGP 1206, 885012008024
designator C?, comment 330 pF
WCAP-CSGP MLCC, NP0, 1206, 330 pF,25Vdc; Manufacturer: Wurth Elektronik; partNo: 885012008024; E-mail: libraries@we-online.com
footprint WCAP-CSGP 1206, H=0.8mm
pins: 1, 2

## WCAP-CSGP 1206, 885012008025
designator C?, comment 470 pF
WCAP-CSGP MLCC, NP0, 1206, 470 pF,25Vdc; Manufacturer: Wurth Elektronik; partNo: 885012008025; E-mail: libraries@we-online.com
footprint WCAP-CSGP 1206, H=0.8mm
pins: 1, 2

## WCAP-CSGP 1206, 885012008026
designator C?, comment 1000 pF
WCAP-CSGP MLCC, NP0, 1206, 1000 pF,25Vdc; Manufacturer: Wurth Elektronik; partNo: 885012008026; E-mail: libraries@we-online.com
footprint WCAP-CSGP 1206, H=0.8mm
pins: 1, 2

## WCAP-CSGP 1206, 885012008027
designator C?, comment 2200 pF
WCAP-CSGP MLCC, NP0, 1206, 2200 pF,25Vdc; Manufacturer: Wurth Elektronik; partNo: 885012008027; E-mail: libraries@we-online.com
footprint WCAP-CSGP 1206, H=0.8mm
pins: 1, 2

## WCAP-CSGP 1206, 885012008028
designator C?, comment 4700 pF
WCAP-CSGP MLCC, NP0, 1206, 4700 pF,25Vdc; Manufacturer: Wurth Elektronik; partNo: 885012008028; E-mail: libraries@we-online.com
footprint WCAP-CSGP 1206, H=0.8mm
pins: 1, 2

## WCAP-CSGP 1206, 885012008029
designator C?, comment 6800 pF
WCAP-CSGP MLCC, NP0, 1206, 6800 pF,25Vdc; Manufacturer: Wurth Elektronik; partNo: 885012008029; E-mail: libraries@we-online.com
footprint WCAP-CSGP 1206, H=0.95mm
pins: 1, 2

## WCAP-CSGP 1206, 885012008030
designator C?, comment 10000 pF
WCAP-CSGP MLCC, NP0, 1206, 10000 pF,25Vdc; Manufacturer: Wurth Elektronik; partNo: 885012008030; E-mail: libraries@we-online.com
footprint WCAP-CSGP 1206, H=1.25mm
pins: 1, 2

## WCAP-CSGP 1206, 885012008031
designator C?, comment 1 pF
WCAP-CSGP MLCC, NP0, 1206, 1 pF,50Vdc; Manufacturer: Wurth Elektronik; partNo: 885012008031; E-mail: libraries@we-online.com
footprint WCAP-CSGP 1206, H=0.8mm
pins: 1, 2

## WCAP-CSGP 1206, 885012008032
designator C?, comment 1.5 pF
WCAP-CSGP MLCC, NP0, 1206, 1.5 pF,50Vdc; Manufacturer: Wurth Elektronik; partNo: 885012008032; E-mail: libraries@we-online.com
footprint WCAP-CSGP 1206, H=0.8mm
pins: 1, 2

## WCAP-CSGP 1206, 885012008033
designator C?, comment 2.2 pF
WCAP-CSGP MLCC, NP0, 1206, 2.2 pF,50Vdc; Manufacturer: Wurth Elektronik; partNo: 885012008033; E-mail: libraries@we-online.com
footprint WCAP-CSGP 1206, H=0.8mm
pins: 1, 2

## WCAP-CSGP 1206, 885012008034
designator C?, comment 3.3 pF
WCAP-CSGP MLCC, NP0, 1206, 3.3 pF,50Vdc; Manufacturer: Wurth Elektronik; partNo: 885012008034; E-mail: libraries@we-online.com
footprint WCAP-CSGP 1206, H=0.8mm
pins: 1, 2

## WCAP-CSGP 1206, 885012008035
designator C?, comment 4.7 pF
WCAP-CSGP MLCC, NP0, 1206, 4.7 pF,50Vdc; Manufacturer: Wurth Elektronik; partNo: 885012008035; E-mail: libraries@we-online.com
footprint WCAP-CSGP 1206, H=0.8mm
pins: 1, 2

## WCAP-CSGP 1206, 885012008036
designator C?, comment 6.8 pF
WCAP-CSGP MLCC, NP0, 1206, 6.8 pF,50Vdc; Manufacturer: Wurth Elektronik; partNo: 885012008036; E-mail: libraries@we-online.com
footprint WCAP-CSGP 1206, H=0.8mm
pins: 1, 2

## WCAP-CSGP 1206, 885012008037
designator C?, comment 10 pF
WCAP-CSGP MLCC, NP0, 1206, 10 pF,50Vdc; Manufacturer: Wurth Elektronik; partNo: 885012008037; E-mail: libraries@we-online.com
footprint WCAP-CSGP 1206, H=0.8mm
pins: 1, 2

## WCAP-CSGP 1206, 885012008038
designator C?, comment 15 pF
WCAP-CSGP MLCC, NP0, 1206, 15 pF,50Vdc; Manufacturer: Wurth Elektronik; partNo: 885012008038; E-mail: libraries@we-online.com
footprint WCAP-CSGP 1206, H=0.8mm
pins: 1, 2

## WCAP-CSGP 1206, 885012008039
designator C?, comment 22 pF
WCAP-CSGP MLCC, NP0, 1206, 22 pF,50Vdc; Manufacturer: Wurth Elektronik; partNo: 885012008039; E-mail: libraries@we-online.com
footprint WCAP-CSGP 1206, H=0.8mm
pins: 1, 2

## WCAP-CSGP 1206, 885012008040
designator C?, comment 33 pF
WCAP-CSGP MLCC, NP0, 1206, 33 pF,50Vdc; Manufacturer: Wurth Elektronik; partNo: 885012008040; E-mail: libraries@we-online.com
footprint WCAP-CSGP 1206, H=0.8mm
pins: 1, 2

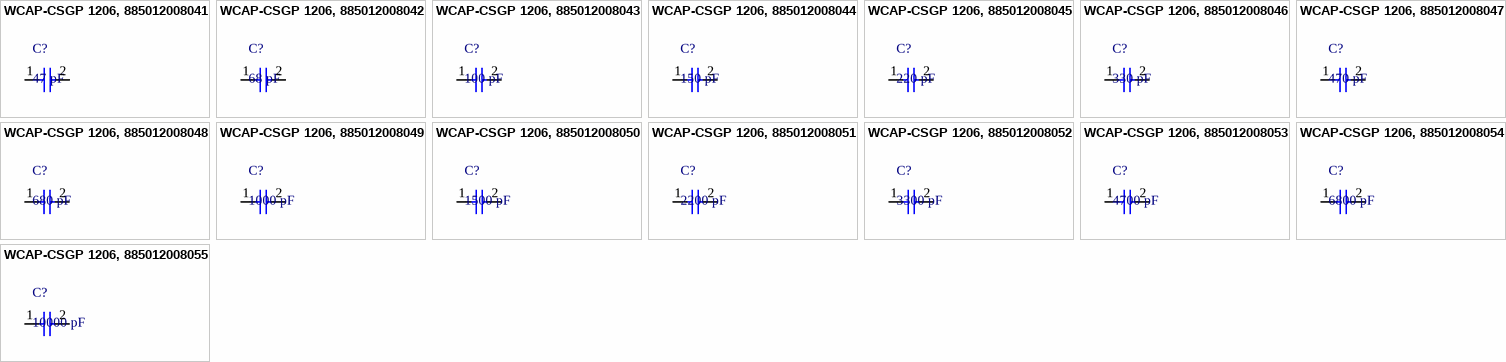
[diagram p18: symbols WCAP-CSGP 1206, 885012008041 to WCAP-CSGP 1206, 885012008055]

## WCAP-CSGP 1206, 885012008041
designator C?, comment 47 pF
WCAP-CSGP MLCC, NP0, 1206, 47 pF,50Vdc; Manufacturer: Wurth Elektronik; partNo: 885012008041; E-mail: libraries@we-online.com
footprint WCAP-CSGP 1206, H=0.8mm
pins: 1, 2

## WCAP-CSGP 1206, 885012008042
designator C?, comment 68 pF
WCAP-CSGP MLCC, NP0, 1206, 68 pF,50Vdc; Manufacturer: Wurth Elektronik; partNo: 885012008042; E-mail: libraries@we-online.com
footprint WCAP-CSGP 1206, H=0.8mm
pins: 1, 2

## WCAP-CSGP 1206, 885012008043
designator C?, comment 100 pF
WCAP-CSGP MLCC, NP0, 1206, 100 pF,50Vdc; Manufacturer: Wurth Elektronik; partNo: 885012008043; E-mail: libraries@we-online.com
footprint WCAP-CSGP 1206, H=0.8mm
pins: 1, 2

## WCAP-CSGP 1206, 885012008044
designator C?, comment 150 pF
WCAP-CSGP MLCC, NP0, 1206, 150 pF,50Vdc; Manufacturer: Wurth Elektronik; partNo: 885012008044; E-mail: libraries@we-online.com
footprint WCAP-CSGP 1206, H=0.8mm
pins: 1, 2

## WCAP-CSGP 1206, 885012008045
designator C?, comment 220 pF
WCAP-CSGP MLCC, NP0, 1206, 220 pF,50Vdc; Manufacturer: Wurth Elektronik; partNo: 885012008045; E-mail: libraries@we-online.com
footprint WCAP-CSGP 1206, H=0.8mm
pins: 1, 2

## WCAP-CSGP 1206, 885012008046
designator C?, comment 330 pF
WCAP-CSGP MLCC, NP0, 1206, 330 pF,50Vdc; Manufacturer: Wurth Elektronik; partNo: 885012008046; E-mail: libraries@we-online.com
footprint WCAP-CSGP 1206, H=0.8mm
pins: 1, 2

## WCAP-CSGP 1206, 885012008047
designator C?, comment 470 pF
WCAP-CSGP MLCC, NP0, 1206, 470 pF,50Vdc; Manufacturer: Wurth Elektronik; partNo: 885012008047; E-mail: libraries@we-online.com
footprint WCAP-CSGP 1206, H=0.8mm
pins: 1, 2

## WCAP-CSGP 1206, 885012008048
designator C?, comment 680 pF
WCAP-CSGP MLCC, NP0, 1206, 680 pF,50Vdc; Manufacturer: Wurth Elektronik; partNo: 885012008048; E-mail: libraries@we-online.com
footprint WCAP-CSGP 1206, H=0.8mm
pins: 1, 2

## WCAP-CSGP 1206, 885012008049
designator C?, comment 1000 pF
WCAP-CSGP MLCC, NP0, 1206, 1000 pF,50Vdc; Manufacturer: Wurth Elektronik; partNo: 885012008049; E-mail: libraries@we-online.com
footprint WCAP-CSGP 1206, H=0.8mm
pins: 1, 2

## WCAP-CSGP 1206, 885012008050
designator C?, comment 1500 pF
WCAP-CSGP MLCC, NP0, 1206, 1500 pF,50Vdc; Manufacturer: Wurth Elektronik; partNo: 885012008050; E-mail: libraries@we-online.com
footprint WCAP-CSGP 1206, H=0.8mm
pins: 1, 2

## WCAP-CSGP 1206, 885012008051
designator C?, comment 2200 pF
WCAP-CSGP MLCC, NP0, 1206, 2200 pF,50Vdc; Manufacturer: Wurth Elektronik; partNo: 885012008051; E-mail: libraries@we-online.com
footprint WCAP-CSGP 1206, H=0.8mm
pins: 1, 2

## WCAP-CSGP 1206, 885012008052
designator C?, comment 3300 pF
WCAP-CSGP MLCC, NP0, 1206, 3300 pF,50Vdc; Manufacturer: Wurth Elektronik; partNo: 885012008052; E-mail: libraries@we-online.com
footprint WCAP-CSGP 1206, H=0.8mm
pins: 1, 2

## WCAP-CSGP 1206, 885012008053
designator C?, comment 4700 pF
WCAP-CSGP MLCC, NP0, 1206, 4700 pF,50Vdc; Manufacturer: Wurth Elektronik; partNo: 885012008053; E-mail: libraries@we-online.com
footprint WCAP-CSGP 1206, H=0.8mm
pins: 1, 2

## WCAP-CSGP 1206, 885012008054
designator C?, comment 6800 pF
WCAP-CSGP MLCC, NP0, 1206, 6800 pF,50Vdc; Manufacturer: Wurth Elektronik; partNo: 885012008054; E-mail: libraries@we-online.com
footprint WCAP-CSGP 1206, H=0.95mm
pins: 1, 2

## WCAP-CSGP 1206, 885012008055
designator C?, comment 10000 pF
WCAP-CSGP MLCC, NP0, 1206, 10000 pF,50Vdc; Manufacturer: Wurth Elektronik; partNo: 885012008055; E-mail: libraries@we-online.com
footprint WCAP-CSGP 1206, H=1.25mm
pins: 1, 2


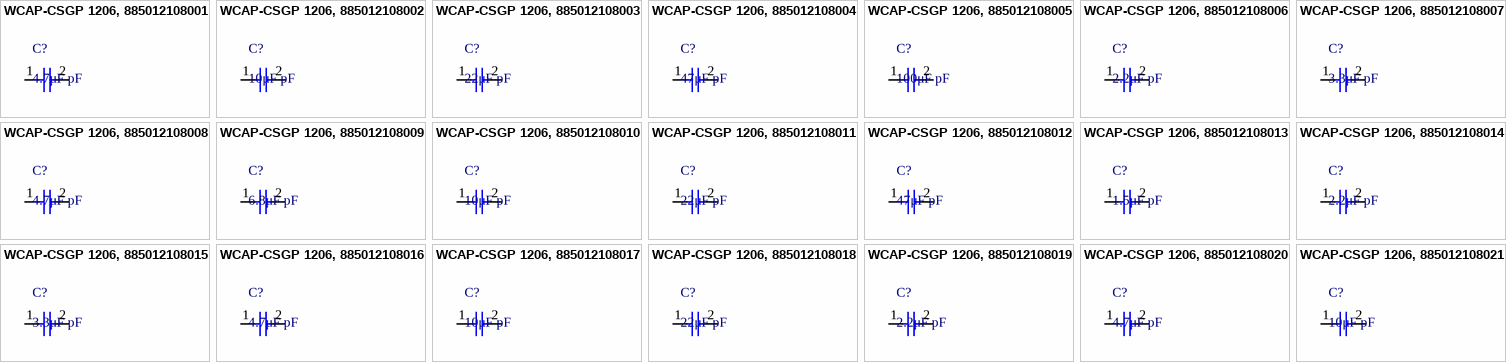
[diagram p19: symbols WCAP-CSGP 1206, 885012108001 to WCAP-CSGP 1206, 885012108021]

## WCAP-CSGP 1206, 885012108001
designator C?, comment 4.7μF pF
WCAP-CSGP MLCC, X5R, 1206, 4.7μF pF,6.3Vdc; Manufacturer: Wurth Elektronik; partNo: 885012108001; E-mail: libraries@we-online.com
footprint WCAP-CSGP 1206, H=1.6mm
pins: 1, 2

## WCAP-CSGP 1206, 885012108002
designator C?, comment 10μF pF
WCAP-CSGP MLCC, X5R, 1206, 10μF pF,6.3Vdc; Manufacturer: Wurth Elektronik; partNo: 885012108002; E-mail: libraries@we-online.com
footprint WCAP-CSGP 1206, H=1.6mm
pins: 1, 2

## WCAP-CSGP 1206, 885012108003
designator C?, comment 22μF pF
WCAP-CSGP MLCC, X5R, 1206, 22μF pF,6.3Vdc; Manufacturer: Wurth Elektronik; partNo: 885012108003; E-mail: libraries@we-online.com
footprint WCAP-CSGP 1206, H=1.6mm
pins: 1, 2

## WCAP-CSGP 1206, 885012108004
designator C?, comment 47μF pF
WCAP-CSGP MLCC, X5R, 1206, 47μF pF,6.3Vdc; Manufacturer: Wurth Elektronik; partNo: 885012108004; E-mail: libraries@we-online.com
footprint WCAP-CSGP 1206, H=1.6mm
pins: 1, 2

## WCAP-CSGP 1206, 885012108005
designator C?, comment 100μF pF
WCAP-CSGP MLCC, X5R, 1206, 100μF pF,6.3Vdc; Manufacturer: Wurth Elektronik; partNo: 885012108005; E-mail: libraries@we-online.com
footprint WCAP-CSGP 1206, H=1.6mm
pins: 1, 2

## WCAP-CSGP 1206, 885012108006
designator C?, comment 2.2μF pF
WCAP-CSGP MLCC, X5R, 1206, 2.2μF pF,10Vdc; Manufacturer: Wurth Elektronik; partNo: 885012108006; E-mail: libraries@we-online.com
footprint WCAP-CSGP 1206, H=1.15mm
pins: 1, 2

## WCAP-CSGP 1206, 885012108007
designator C?, comment 3.3μF pF
WCAP-CSGP MLCC, X5R, 1206, 3.3μF pF,10Vdc; Manufacturer: Wurth Elektronik; partNo: 885012108007; E-mail: libraries@we-online.com
footprint WCAP-CSGP 1206, H=1.6mm
pins: 1, 2

## WCAP-CSGP 1206, 885012108008
designator C?, comment 4.7μF pF
WCAP-CSGP MLCC, X5R, 1206, 4.7μF pF,10Vdc; Manufacturer: Wurth Elektronik; partNo: 885012108008; E-mail: libraries@we-online.com
footprint WCAP-CSGP 1206, H=1.6mm
pins: 1, 2

## WCAP-CSGP 1206, 885012108009
designator C?, comment 6.8μF pF
WCAP-CSGP MLCC, X5R, 1206, 6.8μF pF,10Vdc; Manufacturer: Wurth Elektronik; partNo: 885012108009; E-mail: libraries@we-online.com
footprint WCAP-CSGP 1206, H=1.6mm
pins: 1, 2

## WCAP-CSGP 1206, 885012108010
designator C?, comment 10μF pF
WCAP-CSGP MLCC, X5R, 1206, 10μF pF,10Vdc; Manufacturer: Wurth Elektronik; partNo: 885012108010; E-mail: libraries@we-online.com
footprint WCAP-CSGP 1206, H=1.6mm
pins: 1, 2

## WCAP-CSGP 1206, 885012108011
designator C?, comment 22μF pF
WCAP-CSGP MLCC, X5R, 1206, 22μF pF,10Vdc; Manufacturer: Wurth Elektronik; partNo: 885012108011; E-mail: libraries@we-online.com
footprint WCAP-CSGP 1206, H=1.6mm
pins: 1, 2

## WCAP-CSGP 1206, 885012108012
designator C?, comment 47μF pF
WCAP-CSGP MLCC, X5R, 1206, 47μF pF,10Vdc; Manufacturer: Wurth Elektronik; partNo: 885012108012; E-mail: libraries@we-online.com
footprint WCAP-CSGP 1206, H=1.6mm
pins: 1, 2

## WCAP-CSGP 1206, 885012108013
designator C?, comment 1.5μF pF
WCAP-CSGP MLCC, X5R, 1206, 1.5μF pF,16Vdc; Manufacturer: Wurth Elektronik; partNo: 885012108013; E-mail: libraries@we-online.com
footprint WCAP-CSGP 1206, H=1.15mm
pins: 1, 2

## WCAP-CSGP 1206, 885012108014
designator C?, comment 2.2μF pF
WCAP-CSGP MLCC, X5R, 1206, 2.2μF pF,16Vdc; Manufacturer: Wurth Elektronik; partNo: 885012108014; E-mail: libraries@we-online.com
footprint WCAP-CSGP 1206, H=1.15mm
pins: 1, 2

## WCAP-CSGP 1206, 885012108015
designator C?, comment 3.3μF pF
WCAP-CSGP MLCC, X5R, 1206, 3.3μF pF,16Vdc; Manufacturer: Wurth Elektronik; partNo: 885012108015; E-mail: libraries@we-online.com
footprint WCAP-CSGP 1206, H=1.6mm
pins: 1, 2

## WCAP-CSGP 1206, 885012108016
designator C?, comment 4.7μF pF
WCAP-CSGP MLCC, X5R, 1206, 4.7μF pF,16Vdc; Manufacturer: Wurth Elektronik; partNo: 885012108016; E-mail: libraries@we-online.com
footprint WCAP-CSGP 1206, H=1.6mm
pins: 1, 2

## WCAP-CSGP 1206, 885012108017
designator C?, comment 10μF pF
WCAP-CSGP MLCC, X5R, 1206, 10μF pF,16Vdc; Manufacturer: Wurth Elektronik; partNo: 885012108017; E-mail: libraries@we-online.com
footprint WCAP-CSGP 1206, H=1.6mm
pins: 1, 2

## WCAP-CSGP 1206, 885012108018
designator C?, comment 22μF pF
WCAP-CSGP MLCC, X5R, 1206, 22μF pF,16Vdc; Manufacturer: Wurth Elektronik; partNo: 885012108018; E-mail: libraries@we-online.com
footprint WCAP-CSGP 1206, H=1.6mm
pins: 1, 2

## WCAP-CSGP 1206, 885012108019
designator C?, comment 2.2μF pF
WCAP-CSGP MLCC, X5R, 1206, 2.2μF pF,25Vdc; Manufacturer: Wurth Elektronik; partNo: 885012108019; E-mail: libraries@we-online.com
footprint WCAP-CSGP 1206, H=1.6mm
pins: 1, 2

## WCAP-CSGP 1206, 885012108020
designator C?, comment 4.7μF pF
WCAP-CSGP MLCC, X5R, 1206, 4.7μF pF,25Vdc; Manufacturer: Wurth Elektronik; partNo: 885012108020; E-mail: libraries@we-online.com
footprint WCAP-CSGP 1206, H=1.6mm
pins: 1, 2

## WCAP-CSGP 1206, 885012108021
designator C?, comment 10μF pF
WCAP-CSGP MLCC, X5R, 1206, 10μF pF,25Vdc; Manufacturer: Wurth Elektronik; partNo: 885012108021; E-mail: libraries@we-online.com
footprint WCAP-CSGP 1206, H=1.6mm
pins: 1, 2


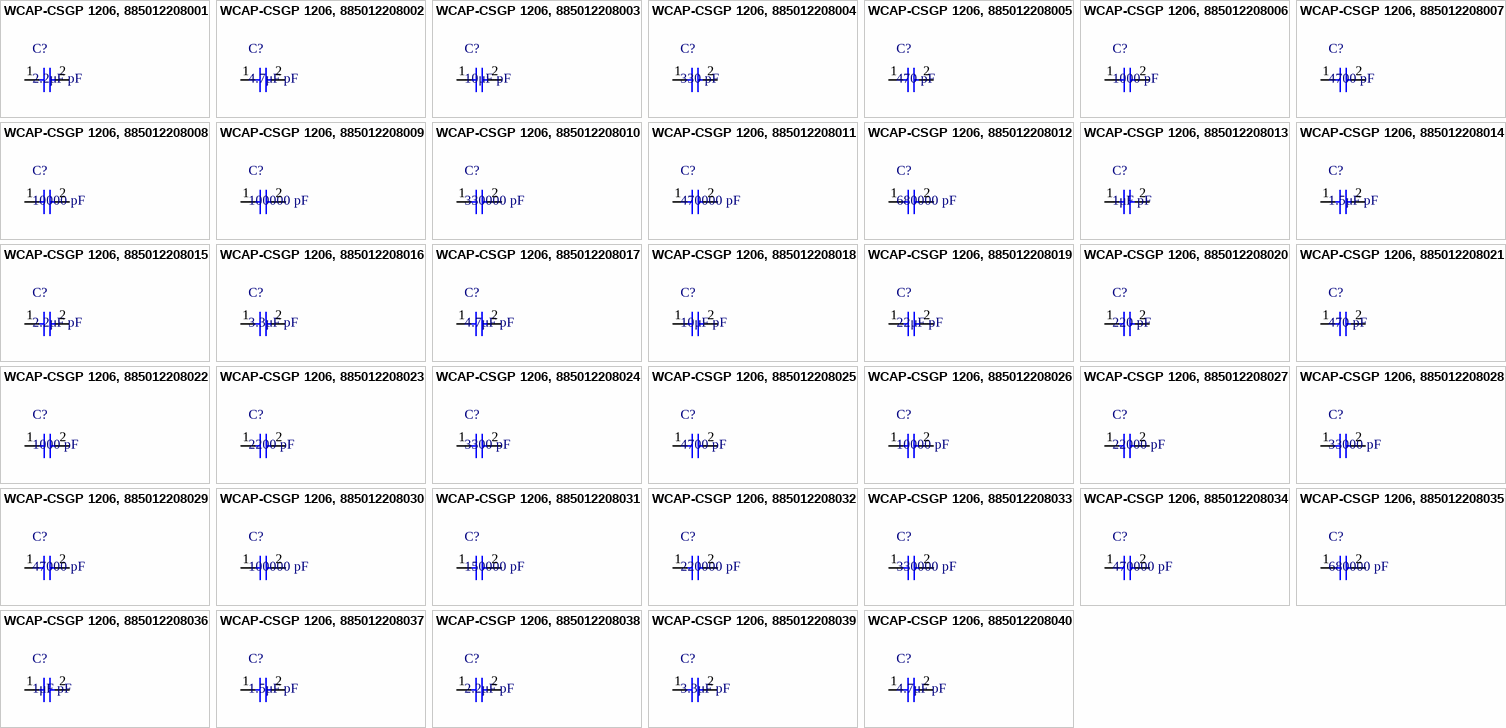
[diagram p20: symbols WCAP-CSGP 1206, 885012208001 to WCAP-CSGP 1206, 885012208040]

## WCAP-CSGP 1206, 885012208001
designator C?, comment 2.2μF pF
WCAP-CSGP MLCC, X7R, 1206, 2.2μF pF,6.3Vdc; Manufacturer: Wurth Elektronik; partNo: 885012208001; E-mail: libraries@we-online.com
footprint WCAP-CSGP 1206, H=1.15mm
pins: 1, 2

## WCAP-CSGP 1206, 885012208002
designator C?, comment 4.7μF pF
WCAP-CSGP MLCC, X7R, 1206, 4.7μF pF,6.3Vdc; Manufacturer: Wurth Elektronik; partNo: 885012208002; E-mail: libraries@we-online.com
footprint WCAP-CSGP 1206, H=1.6mm
pins: 1, 2

## WCAP-CSGP 1206, 885012208003
designator C?, comment 10μF pF
WCAP-CSGP MLCC, X7R, 1206, 10μF pF,6.3Vdc; Manufacturer: Wurth Elektronik; partNo: 885012208003; E-mail: libraries@we-online.com
footprint WCAP-CSGP 1206, H=1.6mm
pins: 1, 2

## WCAP-CSGP 1206, 885012208004
designator C?, comment 330 pF
WCAP-CSGP MLCC, X7R, 1206, 330 pF,10Vdc; Manufacturer: Wurth Elektronik; partNo: 885012208004; E-mail: libraries@we-online.com
footprint WCAP-CSGP 1206, H=0.8mm
pins: 1, 2

## WCAP-CSGP 1206, 885012208005
designator C?, comment 470 pF
WCAP-CSGP MLCC, X7R, 1206, 470 pF,10Vdc; Manufacturer: Wurth Elektronik; partNo: 885012208005; E-mail: libraries@we-online.com
footprint WCAP-CSGP 1206, H=0.8mm
pins: 1, 2

## WCAP-CSGP 1206, 885012208006
designator C?, comment 1000 pF
WCAP-CSGP MLCC, X7R, 1206, 1000 pF,10Vdc; Manufacturer: Wurth Elektronik; partNo: 885012208006; E-mail: libraries@we-online.com
footprint WCAP-CSGP 1206, H=0.8mm
pins: 1, 2

## WCAP-CSGP 1206, 885012208007
designator C?, comment 4700 pF
WCAP-CSGP MLCC, X7R, 1206, 4700 pF,10Vdc; Manufacturer: Wurth Elektronik; partNo: 885012208007; E-mail: libraries@we-online.com
footprint WCAP-CSGP 1206, H=0.8mm
pins: 1, 2

## WCAP-CSGP 1206, 885012208008
designator C?, comment 10000 pF
WCAP-CSGP MLCC, X7R, 1206, 10000 pF,10Vdc; Manufacturer: Wurth Elektronik; partNo: 885012208008; E-mail: libraries@we-online.com
footprint WCAP-CSGP 1206, H=0.8mm
pins: 1, 2

## WCAP-CSGP 1206, 885012208009
designator C?, comment 100000 pF
WCAP-CSGP MLCC, X7R, 1206, 100000 pF,10Vdc; Manufacturer: Wurth Elektronik; partNo: 885012208009; E-mail: libraries@we-online.com
footprint WCAP-CSGP 1206, H=0.8mm
pins: 1, 2

## WCAP-CSGP 1206, 885012208010
designator C?, comment 330000 pF
WCAP-CSGP MLCC, X7R, 1206, 330000 pF,10Vdc; Manufacturer: Wurth Elektronik; partNo: 885012208010; E-mail: libraries@we-online.com
footprint WCAP-CSGP 1206, H=0.95mm
pins: 1, 2

## WCAP-CSGP 1206, 885012208011
designator C?, comment 470000 pF
WCAP-CSGP MLCC, X7R, 1206, 470000 pF,10Vdc; Manufacturer: Wurth Elektronik; partNo: 885012208011; E-mail: libraries@we-online.com
footprint WCAP-CSGP 1206, H=1.15mm
pins: 1, 2

## WCAP-CSGP 1206, 885012208012
designator C?, comment 680000 pF
WCAP-CSGP MLCC, X7R, 1206, 680000 pF,10Vdc; Manufacturer: Wurth Elektronik; partNo: 885012208012; E-mail: libraries@we-online.com
footprint WCAP-CSGP 1206, H=1.15mm
pins: 1, 2

## WCAP-CSGP 1206, 885012208013
designator C?, comment 1μF pF
WCAP-CSGP MLCC, X7R, 1206, 1μF pF,10Vdc; Manufacturer: Wurth Elektronik; partNo: 885012208013; E-mail: libraries@we-online.com
footprint WCAP-CSGP 1206, H=1.15mm
pins: 1, 2

## WCAP-CSGP 1206, 885012208014
designator C?, comment 1.5μF pF
WCAP-CSGP MLCC, X7R, 1206, 1.5μF pF,10Vdc; Manufacturer: Wurth Elektronik; partNo: 885012208014; E-mail: libraries@we-online.com
footprint WCAP-CSGP 1206, H=1.15mm
pins: 1, 2

## WCAP-CSGP 1206, 885012208015
designator C?, comment 2.2μF pF
WCAP-CSGP MLCC, X7R, 1206, 2.2μF pF,10Vdc; Manufacturer: Wurth Elektronik; partNo: 885012208015; E-mail: libraries@we-online.com
footprint WCAP-CSGP 1206, H=1.15mm
pins: 1, 2

## WCAP-CSGP 1206, 885012208016
designator C?, comment 3.3μF pF
WCAP-CSGP MLCC, X7R, 1206, 3.3μF pF,10Vdc; Manufacturer: Wurth Elektronik; partNo: 885012208016; E-mail: libraries@we-online.com
footprint WCAP-CSGP 1206, H=1.6mm
pins: 1, 2

## WCAP-CSGP 1206, 885012208017
designator C?, comment 4.7μF pF
WCAP-CSGP MLCC, X7R, 1206, 4.7μF pF,10Vdc; Manufacturer: Wurth Elektronik; partNo: 885012208017; E-mail: libraries@we-online.com
footprint WCAP-CSGP 1206, H=1.6mm
pins: 1, 2

## WCAP-CSGP 1206, 885012208018
designator C?, comment 10μF pF
WCAP-CSGP MLCC, X7R, 1206, 10μF pF,10Vdc; Manufacturer: Wurth Elektronik; partNo: 885012208018; E-mail: libraries@we-online.com
footprint WCAP-CSGP 1206, H=1.6mm
pins: 1, 2

## WCAP-CSGP 1206, 885012208019
designator C?, comment 22μF pF
WCAP-CSGP MLCC, X7R, 1206, 22μF pF,10Vdc; Manufacturer: Wurth Elektronik; partNo: 885012208019; E-mail: libraries@we-online.com
footprint WCAP-CSGP 1206, H=1.6mm
pins: 1, 2

## WCAP-CSGP 1206, 885012208020
designator C?, comment 220 pF
WCAP-CSGP MLCC, X7R, 1206, 220 pF,16Vdc; Manufacturer: Wurth Elektronik; partNo: 885012208020; E-mail: libraries@we-online.com
footprint WCAP-CSGP 1206, H=0.8mm
pins: 1, 2

## WCAP-CSGP 1206, 885012208021
designator C?, comment 470 pF
WCAP-CSGP MLCC, X7R, 1206, 470 pF,16Vdc; Manufacturer: Wurth Elektronik; partNo: 885012208021; E-mail: libraries@we-online.com
footprint WCAP-CSGP 1206, H=0.8mm
pins: 1, 2

## WCAP-CSGP 1206, 885012208022
designator C?, comment 1000 pF
WCAP-CSGP MLCC, X7R, 1206, 1000 pF,16Vdc; Manufacturer: Wurth Elektronik; partNo: 885012208022; E-mail: libraries@we-online.com
footprint WCAP-CSGP 1206, H=0.8mm
pins: 1, 2

## WCAP-CSGP 1206, 885012208023
designator C?, comment 2200 pF
WCAP-CSGP MLCC, X7R, 1206, 2200 pF,16Vdc; Manufacturer: Wurth Elektronik; partNo: 885012208023; E-mail: libraries@we-online.com
footprint WCAP-CSGP 1206, H=0.8mm
pins: 1, 2

## WCAP-CSGP 1206, 885012208024
designator C?, comment 3300 pF
WCAP-CSGP MLCC, X7R, 1206, 3300 pF,16Vdc; Manufacturer: Wurth Elektronik; partNo: 885012208024; E-mail: libraries@we-online.com
footprint WCAP-CSGP 1206, H=0.8mm
pins: 1, 2

## WCAP-CSGP 1206, 885012208025
designator C?, comment 4700 pF
WCAP-CSGP MLCC, X7R, 1206, 4700 pF,16Vdc; Manufacturer: Wurth Elektronik; partNo: 885012208025; E-mail: libraries@we-online.com
footprint WCAP-CSGP 1206, H=0.8mm
pins: 1, 2

## WCAP-CSGP 1206, 885012208026
designator C?, comment 10000 pF
WCAP-CSGP MLCC, X7R, 1206, 10000 pF,16Vdc; Manufacturer: Wurth Elektronik; partNo: 885012208026; E-mail: libraries@we-online.com
footprint WCAP-CSGP 1206, H=0.8mm
pins: 1, 2

## WCAP-CSGP 1206, 885012208027
designator C?, comment 22000 pF
WCAP-CSGP MLCC, X7R, 1206, 22000 pF,16Vdc; Manufacturer: Wurth Elektronik; partNo: 885012208027; E-mail: libraries@we-online.com
footprint WCAP-CSGP 1206, H=0.8mm
pins: 1, 2

## WCAP-CSGP 1206, 885012208028
designator C?, comment 33000 pF
WCAP-CSGP MLCC, X7R, 1206, 33000 pF,16Vdc; Manufacturer: Wurth Elektronik; partNo: 885012208028; E-mail: libraries@we-online.com
footprint WCAP-CSGP 1206, H=0.8mm
pins: 1, 2

## WCAP-CSGP 1206, 885012208029
designator C?, comment 47000 pF
WCAP-CSGP MLCC, X7R, 1206, 47000 pF,16Vdc; Manufacturer: Wurth Elektronik; partNo: 885012208029; E-mail: libraries@we-online.com
footprint WCAP-CSGP 1206, H=0.8mm
pins: 1, 2

## WCAP-CSGP 1206, 885012208030
designator C?, comment 100000 pF
WCAP-CSGP MLCC, X7R, 1206, 100000 pF,16Vdc; Manufacturer: Wurth Elektronik; partNo: 885012208030; E-mail: libraries@we-online.com
footprint WCAP-CSGP 1206, H=0.8mm
pins: 1, 2

## WCAP-CSGP 1206, 885012208031
designator C?, comment 150000 pF
WCAP-CSGP MLCC, X7R, 1206, 150000 pF,16Vdc; Manufacturer: Wurth Elektronik; partNo: 885012208031; E-mail: libraries@we-online.com
footprint WCAP-CSGP 1206, H=0.95mm
pins: 1, 2

## WCAP-CSGP 1206, 885012208032
designator C?, comment 220000 pF
WCAP-CSGP MLCC, X7R, 1206, 220000 pF,16Vdc; Manufacturer: Wurth Elektronik; partNo: 885012208032; E-mail: libraries@we-online.com
footprint WCAP-CSGP 1206, H=0.95mm
pins: 1, 2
